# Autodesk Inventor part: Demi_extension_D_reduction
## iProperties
Shininess: 64.0
Length Units: 11269
Angle Units: 11279
Time Units: 11290
Mass Units: 11283
Length Display Precision: 3
Angle Display Precision: 2
Compacted: True
Part Number: Demi_extension_D_reduction
Document SubType Name: Modeling
Created: 2008-02
Material: Acier inoxydable, austénitique
Designer: Pascal
Density: 8.03 g/cm^3
Density: 0.0
Volumn: 0.0
Area: 0.0
PropertySet Name: Model Information
Control State: 0
Master: False
Checked Out: False
MATIERE_PIECE: X2CrNi 18-11
OBSERVATIONS: Tôle ep. 15/10
DESIGNATION: Demi-extension droite
Author: Pascal
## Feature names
1. Extrusion1
2. Extrusion2
3. Extrusion3
